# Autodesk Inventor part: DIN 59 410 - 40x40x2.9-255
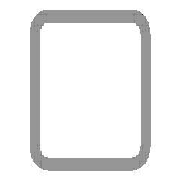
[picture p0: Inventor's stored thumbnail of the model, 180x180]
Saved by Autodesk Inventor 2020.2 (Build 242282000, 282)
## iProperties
Manager: www.cadconsulting.pl
Company: Fabian Stasiak CAD Consulting
_CCFamilyMember: 10
_CCFamilyDisplayName: DIN 59410 (Kwadrat) - Rurki stalowe o przekroju kwadratowym formowane na gorąco
_FrameMemberDoc: Frame Member File
_Version: 15.0.0
_GetPNFromCC: 1
Created: 2015-01
Part Number: DIN 59 410 - 40x40x2.9-255
Material: Stal, miękka
Description: Rurki stalowe o przekroju kwadratowym formowane na gorąco
Document SubType Name: Modellieren
Standard: DIN
Designer: F.Stasiak
Standards Organization: DIN
Language: pl-PL
Size Designation: 40x40x2.9
Categories: <MemberInstance><Categories><Category DisplayName="Kształtowniki konstrukcyjne" InternalName="089c4875-fa83-4c05-b084-43b9cc11f5ed" Mnemonic="GRDR"><CategoryPar
Stock Number: 40x40x2.9
Density: 7.85 g/cm^3
Appearance: Częściowo polerowana
Mass: 818.12 g
Surface Area: 726.927 cm^2
Volume: 104.219 cm^3
Catalog Web Link: www.expertbooks.pl
IsCustomPart: 1
G_L: 255,000 mm
G_W: 40,000 mm
G_H: 40,000 mm
+041DEDD8-2FA7-40C3-B565-5F8A8374DED7+CUTDETAIL1: Wytnij
Author: F.Stasiak
Subject: Zbiór ćwiczeń. Autodesk Inventor 2020. Kurs Professional
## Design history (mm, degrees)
node "Płaszczyzna początkowa"
node "Płaszczyzna końcowa"
sketch "Szkic"
  geometry: L1 (-14.2, 20)-(14.2, 20); L2 (20, 14.2)-(20, -14.2); L3 (14.2, -20)-(-14.2, -20); L4 (-20, -14.2)-(-20, 14.2); L5 (-29.682, 0)-(29.682, 0) reference; L6 (0, -29.682)-(0, 29.682) reference; L7 (-14.2, 17.1)-(14.2, 17.1); L8 (17.1, 14.2)-(17.1, -14.2); L9 (14.2, -17.1)-(-14.2, -17.1); L10 (-17.1, -14.2)-(-17.1, 14.2); A1 r 5.8 centre (-14.2, 14.2) between (-14.2, 20) and (-20, 14.2); A2 r 5.8 centre (14.2, 14.2) between (20, 14.2) and (14.2, 20); A3 r 5.8 centre (14.2, -14.2) between (14.2, -20) and (20, -14.2); A4 r 5.8 centre (-14.2, -14.2) between (-20, -14.2) and (-14.2, -20); A5 r 2.9 centre (-14.2, 14.2) between (-14.2, 17.1) and (-17.1, 14.2); A6 r 2.9 centre (14.2, 14.2) between (17.1, 14.2) and (14.2, 17.1); A7 r 2.9 centre (14.2, -14.2) between (14.2, -17.1) and (17.1, -14.2); A8 r 2.9 centre (-14.2, -14.2) between (-17.1, -14.2) and (-14.2, -17.1); 3 further points
  constraints: 16 end point, 16 point on circle, 8 centre point, 8 tangent, 6 point on line, 4 parallel, 3 equal radius, 3 perpendicular, 1 horizontal, 7 other
  dimensions: "b" = 40 distance of point (-20, 20) point (20, 20); "msp_r" = 5.8 radius of A1 (= 2 x ParT); "d8" = 20 distance between parallel lines of L4 L6 (= d9); "d9" = 20 distance between parallel lines of L3 L5 (= 0.5 x b); "d10" = 2.9 distance between parallel lines of L3 L9 (= ParT)
extrude "Bryła" new body sketch "Szkic" taper "d4" = 0 deg; stored distance "NLG" = 10
node "Driven Length"
  sketch "Sketch2"
    geometry: L1 (0, 0)-(10, 0) reference
    constraints: 2 end point, 1 horizontal
  workplane "Work Plane3"
  sketch "Sketch3"
    geometry: L1 (-2, 25)-(12, 25) reference; L2 (-2, 280)-(12, 280) reference
    dimensions: "d14" = 255 distance between parallel lines of L1 L2 (derived)
node "Płaszczyzna konstrukcyjna4"
feature "Podział1"
node "Płaszczyzna konstrukcyjna5"
feature "Podział2"
body "Solid1"
other parameters: "ParT" = 2.9, "G_OFFSET_START" = -25 [user parameter; used in 1 equation term], "d11" = 25 (= -G_OFFSET_START), "G_L" = 255 (= d14) [user parameter], "d13" = 90 deg
